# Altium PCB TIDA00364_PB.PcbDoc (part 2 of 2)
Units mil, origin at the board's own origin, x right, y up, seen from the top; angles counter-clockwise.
Board outline 10630 x 4425 mil, 2 copper layers (Top Layer, Metal), stack 128.78 mil thick; 244 components, 79 nets, 527 pads, 0 vias.
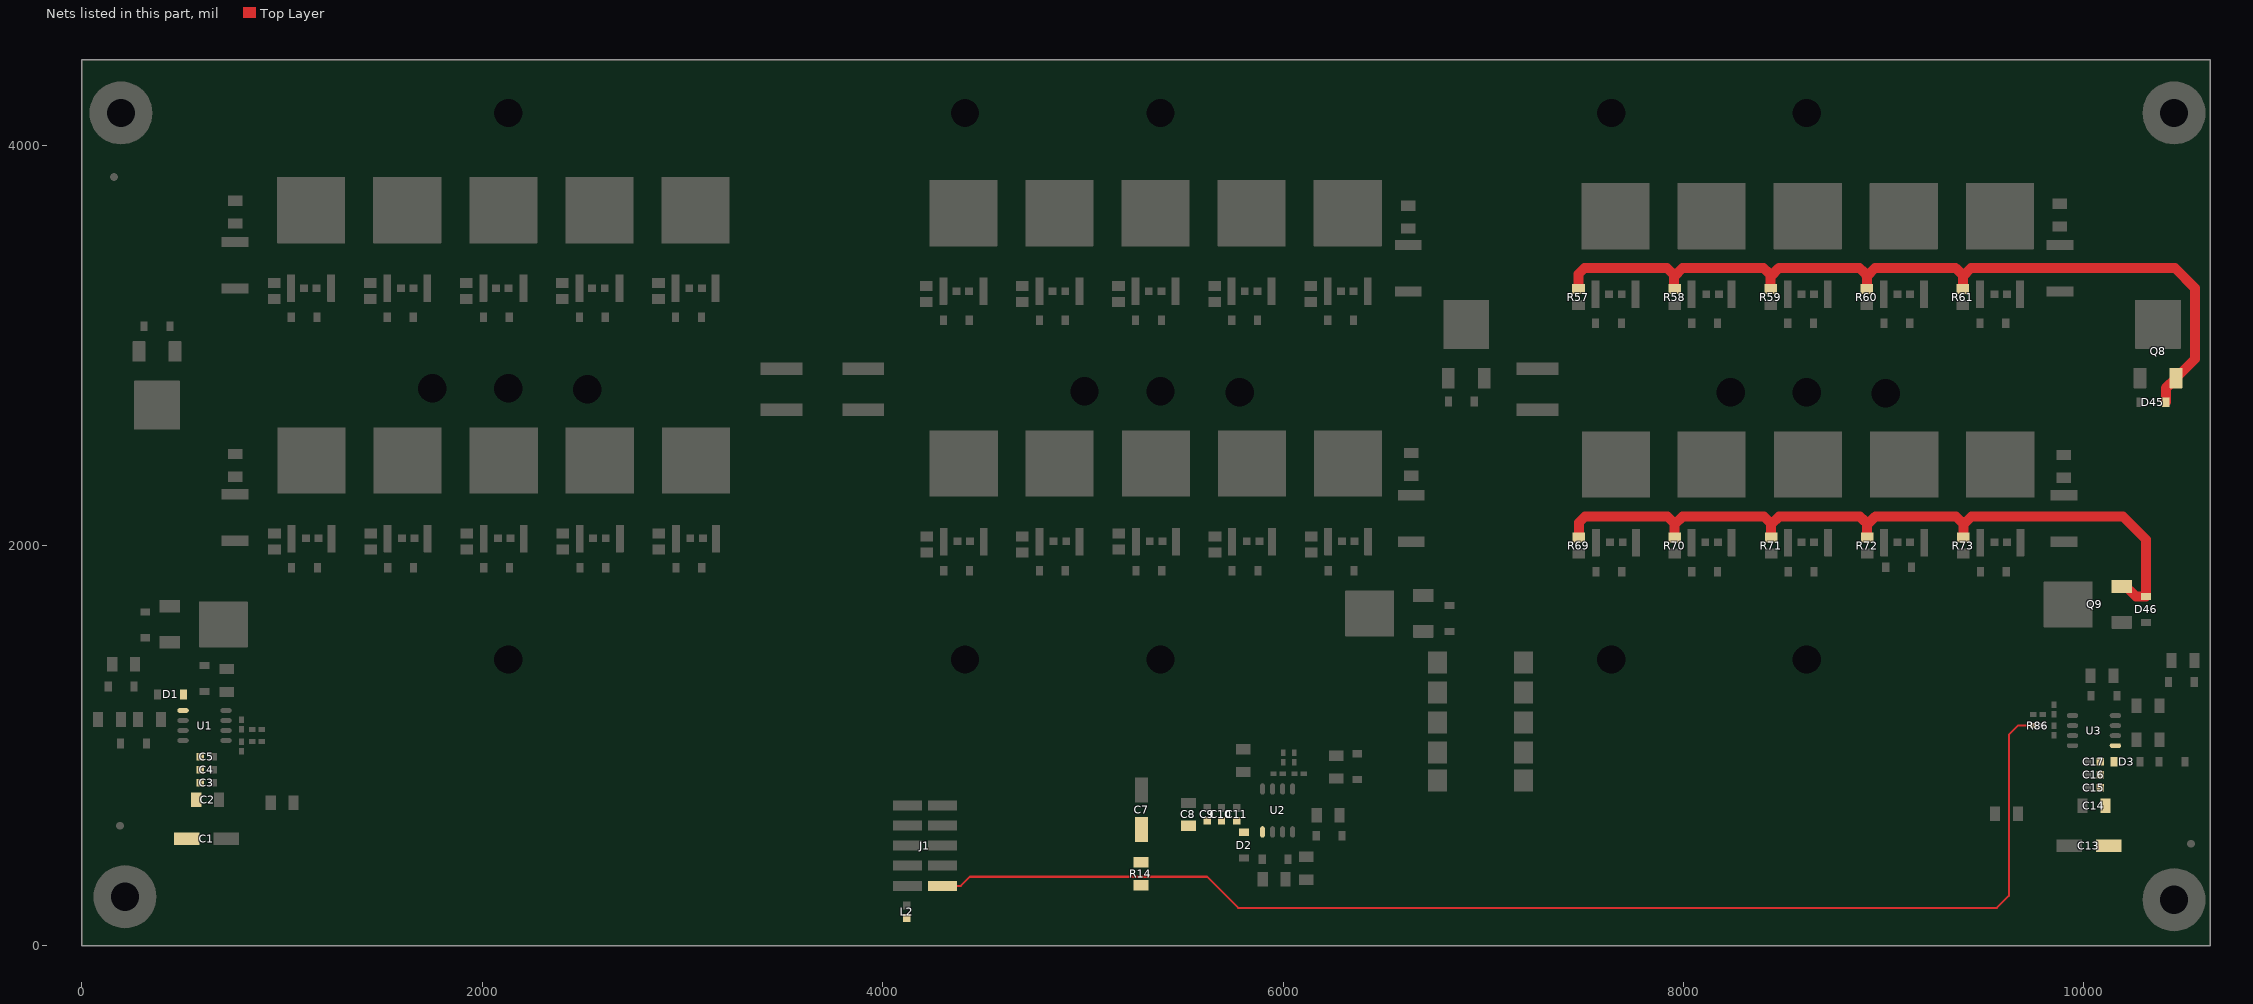
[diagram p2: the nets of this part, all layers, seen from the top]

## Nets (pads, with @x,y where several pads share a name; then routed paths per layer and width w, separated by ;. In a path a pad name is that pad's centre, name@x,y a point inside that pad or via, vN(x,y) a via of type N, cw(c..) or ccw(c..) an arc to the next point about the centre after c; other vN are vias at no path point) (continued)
PHW_PWM_HI_DRV: D45.1 Q8.3 R57.2 R58.2 R59.2 R60.2 R61.2 | length 4225.8
  Top Layer w30: D45.1@10408.94,2715.53 D45.1@10409.23,2715.83
  Top Layer w50: R57.2@7475.28,3280 7475.28,3355.32 7505.75,3385.79 7917.6,3385.79 7937.6,3365.79 7955.89,3347.5 ; R58.2@7953.39,3280 7953.39,3345 7955.89,3347.5 ; R59.2@8435.28,3295 8435.28,3345 8437.78,3347.5 ; R60.2@8915.28,3280 8915.28,3345 8917.78,3347.5 ; R61.2@9395.28,3280 9395.28,3345 9397.78,3347.5 ; D45.1@10408.94,2715.53 10408.94,2785.32 Q8.3@10459.76,2836.14 10555,2931.38 10555,3285 10454.21,3385.79 9436.06,3385.79 9397.78,3347.5 ; 7955.89,3347.5 7994.17,3385.79 8399.49,3385.79 8420.12,3365.16 8437.78,3347.5 ; 8437.78,3347.5 8476.06,3385.79 8879.49,3385.79 8895.75,3369.53 8917.78,3347.5 ; 8917.78,3347.5 8956.06,3385.79 9359.49,3385.79 9384.49,3360.79 9397.78,3347.5
PHW_PWM_LO: J1.10 R86.2 | length 6380.3
  Top Layer w10: J1.10@4297.4,300 4390,300 4435,345 5620,345 5775,190 9565,190 9625,250 9625,1055 9670,1100 R86.2@9746.38,1100
PHW_PWM_LO_DRV: D46.1 Q9.3 R69.2 R70.2 R71.2 R72.2 R73.2 | length 3781.9
  Top Layer w30: Q9.3@10188.86,1794.76 10210.24,1794.76 Q9.3@10232.5,1772.5
  Top Layer w50: R69.2@7477.17,2039.21 7477.17,2114.53 7507.64,2145 7919.49,2145 7939.49,2125 7957.78,2106.71 ; R70.2@7955.28,2039.21 7955.28,2104.21 7957.78,2106.71 ; R71.2@8437.17,2054.21 8437.17,2104.21 8439.67,2106.71 ; R72.2@8917.17,2039.21 8917.17,2104.21 8919.67,2106.71 ; R73.2@9397.17,2039.21 9397.17,2104.21 9399.67,2106.71 ; Q9.3@10232.5,1772.5 10260.53,1744.47 D46.1@10310,1744.47 10310,2030 10195,2145 9437.95,2145 9399.67,2106.71 ; 7957.78,2106.71 7996.06,2145 8401.38,2145 8422.01,2124.37 8439.67,2106.71 ; 8439.67,2106.71 8477.95,2145 8881.38,2145 8897.64,2128.74 8919.67,2106.71 ; 8919.67,2106.71 8957.95,2145 9361.38,2145 9386.38,2120 9399.67,2106.71
VDD: C1.1 C2.1 C3.2 C4.1 C5.1 C7.1 C8.1 C9.2 C10.1 C11.1 C13.1 C14.1 C15.2 C16.1 C17.1 D1.2 D2.2 D3.2 L2.2 R14.1 R14.2 U1.1 U2.1 U3.1
pads on no net: FID1.1 FID2.1 FID3.1 H1. H2. H3. H4. H5. H6. H7. H8. H22.0 H23.0 H26.0 H27.0 H28.0 H29.0 H30.0 H31.0 H32.0 H33.0 H34.0 H35.0 H36.0 H37.0 H38.0

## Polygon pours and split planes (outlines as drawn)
48V on Top Layer "48V_L01_P294" (solid, remove dead copper, pour order 294): 3305,3490 3350,3445 3370,3425 3370,2860 3370,2834.3 3379.3,2825 4000,2825 4020,2845 4020,3440 4045,3465 4050,3470 4340,3470 6470,3470 6495,3495 6495,3655 6510,3670 6750,3670 6765,3655 6765,3495 6780,3480 7100,3480 7130,3450 7140,3440 7140,2860 7140,2835 7150,2825 7365.7,2825 7385.7,2845 7385.7,3129.3 7385,3130 7385,3445 7400,3460 7580,3460 9745,3460 9755,3470 9755,3670 9765,3680 10200,3680 10230,3710 10230,4365 10205,4390 425,4390 405,4370 405,3700 415,3690 895,3690 915,3670 915,3530 955,3490
48V_RTN on Top Layer "48V_RTN_L01_P292" (solid, remove dead copper, pour order 292): 7135,2080 7135,2705 7155,2725 7365.7,2725 7385.7,2705 7390,2700.7 7390,2025 7135,2025
48V_RTN on Top Layer "48V_RTN_L01_P290" (solid, remove dead copper, pour order 290): 3965.98,2735 3405,2735 3375,2705 3370,2700 3370,2585 3370,2135 3330,2095 3310,2075 3310,2070 4050,2070 4055,2075 4020,2110 4020,2210 4020,2725 4010,2735
PHASE_W on Top Layer "PHASE_W_L01_P288" (solid, remove dead copper, pour order 288): 9640,2225 9740,2225 9755,2240 9755,2400 9775,2420 9940,2420 9960,2440 9960,3312.99 9942.99,3330 9600,3330 9590,3320 9590,3045 9575,3030 9335,3030 9315,3050 9310,3055 9310,3100 9310,3310 9290,3330 9120,3330 9110,3320 9110,3135 9110,3040 9100,3030 8855,3030 8835,3050 8830,3055 8830,3225 8830,3315 8810,3335 8640,3335 8630,3325 8630,3040 8620,3030 8365,3030 8350,3045 8350,3320 8340,3330 8160,3330 8150,3320 8150,3035 8145,3030 7885,3030 7870,3045 7870,3300 7845,3325 7680,3325 7670,3315 7670,3045 7655,3030 7500,3030 7460,2990 7460,2245 7480,2225
PHASE_V on Top Layer "PHASE_V_L01_P286" (solid, remove dead copper, pour order 286): 6190,2220 6480,2220 6500,2240 6500,2420 6510,2430 6675,2430 6685,2440 6685,2510 6665,2530 6640,2555 6640,2725 6640,3085 6700,3145 6700,3325 6680,3345 6340,3345 6335,3340 6330,3335 6330,3215 6330,3055 6320,3045 6070,3045 6060,3055 6060,3340 6050,3350 5860,3350 5850,3340 5850,3055 5840,3045 5590,3045 5575,3060 5575,3320 5550,3345 5380,3345 5370,3335 5370,3055 5360,3045 5105,3045 5095,3055 5095,3335 5080,3350 4900,3350 4890,3340 4890,3290 4890,3060 4875,3045 4630,3045 4615,3060 4615,3330 4600,3345 4420,3345 4410,3335 4410,3265 4410,3055 4400,3045 4100,3045 4080,3025 4080,2635 4080,2250 4110,2220 4125,2220 4820,2220
PHASE_U on Top Layer "PHASE_U_L01_P284" (solid, remove dead copper, pour order 284): 875,3320 695,3320 690,3315 690,2440 700,2430 915,2430 925,2420 925,2245 935,2235 3290,2235 3305,2250 3305,3325 3270,3360 3080,3360 3075,3355 3075,3070 3065,3060 2810,3060 2800,3070 2800,3355 2790,3365 2595,3365 2590,3360 2590,3065 2585,3060 2330,3060 2320,3070 2320,3350 2310,3360 2120,3360 2110,3350 2110,3070 2100,3060 1850,3060 1840,3070 1840,3350 1825,3365 1640,3365 1635,3360 1635,3075 1620,3060 1380,3060 1360,3080 1360,3340 1340,3360 1165,3360 1150,3345 1150,3075 1135,3060 890,3060 880,3070 880,3315 875,3320
48V_RTN on Top Layer "Top Layer-No Net 1" (solid, remove dead copper, pour order 254): 159 vertices, not listed, extent 30,165 10585,2110
NetC24_2 on Top Layer "Top Layer-No Net" (solid, remove dead copper, pour order 282): 6565,2390 6715,2390 6720,2385 6720,2215 6715,2210 6565,2210 6560,2215 6560,2385
NetC23_2 on Top Layer "Top Layer-No Net" (solid, remove dead copper, pour order 280): 6560,3640 6710,3640 6715,3635 6715,3460 6710,3455 6555,3455 6550,3460 6550,3635 6555,3640
VDD on Top Layer "VDD_L01_P252" (solid, remove dead copper, pour order 252): 613,460 454,460 454,71 475,50 10170,50 10190,70 10190,290 9705,290 9635,220 9575,160 9545,160 1080,160 965,275 940,300 705,300 645,300 615,330 613,332 613,460
VDD on Top Layer "Top Layer-No Net 1" (solid, pour order 240): 5155,635 5155,400 5165,390 5502,390 5649.64,537.64 5903.64,537.64 5911.64,545.64 5911.64,635.64 5900.64,646.64 5166.64,646.64
VDD on Top Layer "Top Layer-No Net 1" (solid, pour order 238): 4465,325 4275,135 4465,135 5605,135 5795,135 5605,325
48V_RTN on Top Layer "Top Layer-No Net 1" (solid, remove dead copper, pour order 236): 5954.6,752.93 5934.7,752.93 5930,757.64 5930,827.64 5915,842.64 5820,842.64 5815,837.64 5815,685 5800,670 5075,670 5050,645 5050,490 5030,470 5010,470 4385,470 4235,470 4220,485 4220,545 4225,550 4465,550 4475,560 4475,900 5965,900 5965,763.33
48V_RTN on Top Layer "Top Layer-No Net 1" (solid, pour order 234): 864,1151 642,1151 634.39,1143.39 634.39,340.61 645,330 940,330 970,360 970,955 940,985 690,985 675,1000 675,1089 697,1111 876,1111 880,1115 880,1145 875,1150 865,1150
NetJ1_9 on Top Layer "Top Layer-No Net 1" (solid, pour order 232): 4040,345 4195,345 4200,340 4200,190 4190,180 4035,180 4025,190 4025,335 4035,345
NetC18_1 on Top Layer "Top Layer-No Net 1" (solid, pour order 224): 10350,1240 10350,995 10355,990 10465,990 10475,980 10480,975 10480,895 10480,882.5 10485,877.5 10537.5,877.5 10545,885 10545,1220 10520,1245 10355,1245 10350,1240
NetD3_1 on Top Layer "Top Layer-No Net 1" (solid, pour order 222): 10135,1070 10290,1070 10295,1065 10295,978 10311,962 10398,962 10405,955 10405,882.5 10400,877.5 10237.5,877.5 10225,890 10225,1030 10215,1040 10130,1040 10125,1045 10125,1065 10130,1070
VDD on Top Layer "Top Layer-No Net 1" (solid, remove dead copper, pour order 214): 568,940 568,812.98 533.08,778.06 454,698.98 454,482 454,419 470,403 610,403 613,406 613,791 614,792 614,833 614,1179 606,1187 557,1187 546,1198 539,1205 539,1262 539,1292 533,1298 484,1298 474,1288 474,1170 483,1161 549,1161 567,1143 568,1142
NetD1_1 on Top Layer "Top Layer-No Net 1" (solid, pour order 212): 470,1140 530,1140 535,1135 535,1115 530,1110 445,1110 425,1090 370,1035 370,975 362.93,967.93 307.07,967.93 300,975 300,1047.93 305,1052.93 317.93,1052.93 330,1065 335,1070 335,1255 335,1285.86 346.57,1297.43 422.57,1297.43 430,1290 430,1150 440,1140
NetC6_1 on Top Layer "Top Layer-No Net 1" (solid, pour order 210): 170,1175 170,970.49 172.57,967.93 212.93,967.93 225,980 225,1075.73 232.06,1082.79 302.79,1082.79 310,1090 310,1175 305,1180 175,1180
NetD38_1 on Top Layer "Top Layer-No Net 1" (solid, pour order 200): 7537.17,2089.21 7632.17,2089.21 7642.17,2079.21 7647.17,2074.21 7647.17,2009.21 7647.17,1844.21 7627.17,1824.21 7447.17,1824.21 7432.17,1839.21 7432.17,1984.21 7437.17,1989.21 7522.17,1989.21 7532.17,1999.21 7532.17,2084.21 7537.17,2089.21
NetD39_1 on Top Layer "Top Layer-No Net 1" (solid, pour order 198): 8015.28,2089.21 8110.28,2089.21 8120.28,2079.21 8125.28,2074.21 8125.28,2009.21 8125.28,1844.21 8105.28,1824.21 7925.28,1824.21 7910.28,1839.21 7910.28,1984.21 7915.28,1989.21 8000.28,1989.21 8010.28,1999.21 8010.28,2084.21 8015.28,2089.21
NetD40_1 on Top Layer "Top Layer-No Net 1" (solid, pour order 196): 8497.17,2089.21 8592.17,2089.21 8602.17,2079.21 8607.17,2074.21 8607.17,2009.21 8607.17,1844.21 8587.17,1824.21 8407.17,1824.21 8392.17,1839.21 8392.17,1984.21 8397.17,1989.21 8482.17,1989.21 8492.17,1999.21 8492.17,2084.21 8497.17,2089.21
NetD41_1 on Top Layer "Top Layer-No Net 1" (solid, pour order 194): 8977.17,2089.21 9072.17,2089.21 9082.17,2079.21 9087.17,2074.21 9087.17,2009.21 9087.17,1844.21 9067.17,1824.21 8887.17,1824.21 8872.17,1839.21 8872.17,1984.21 8877.17,1989.21 8962.17,1989.21 8972.17,1999.21 8972.17,2084.21 8977.17,2089.21
NetD42_1 on Top Layer "Top Layer-No Net 1" (solid, pour order 192): 9457.17,2089.21 9552.17,2089.21 9562.17,2079.21 9567.17,2074.21 9567.17,2009.21 9567.17,1844.21 9547.17,1824.21 9367.17,1824.21 9352.17,1839.21 9352.17,1984.21 9357.17,1989.21 9442.17,1989.21 9452.17,1999.21 9452.17,2084.21 9457.17,2089.21
NetD37_1 on Top Layer "Top Layer-No Net 1" (solid, pour order 190): 9455.28,3330 9550.28,3330 9560.28,3320 9565.28,3315 9565.28,3250 9565.28,3085 9545.28,3065 9365.28,3065 9350.28,3080 9350.28,3225 9355.28,3230 9440.28,3230 9450.28,3240 9450.28,3325 9455.28,3330
NetD36_1 on Top Layer "Top Layer-No Net 1" (solid, pour order 188): 8975.28,3330 9070.28,3330 9080.28,3320 9085.28,3315 9085.28,3250 9085.28,3085 9065.28,3065 8885.28,3065 8870.28,3080 8870.28,3225 8875.28,3230 8960.28,3230 8970.28,3240 8970.28,3325 8975.28,3330
NetD35_1 on Top Layer "Top Layer-No Net 1" (solid, pour order 186): 8495.28,3330 8590.28,3330 8600.28,3320 8605.28,3315 8605.28,3250 8605.28,3085 8585.28,3065 8405.28,3065 8390.28,3080 8390.28,3225 8395.28,3230 8480.28,3230 8490.28,3240 8490.28,3325 8495.28,3330
NetD34_1 on Top Layer "Top Layer-No Net 1" (solid, pour order 184): 8015.28,3330 8110.28,3330 8120.28,3320 8125.28,3315 8125.28,3250 8125.28,3085 8105.28,3065 7925.28,3065 7910.28,3080 7910.28,3225 7915.28,3230 8000.28,3230 8010.28,3240 8010.28,3325 8015.28,3330
NetD33_1 on Top Layer "Top Layer-No Net 1" (solid, pour order 182): 7535.28,3330 7630.28,3330 7640.28,3320 7645.28,3315 7645.28,3250 7645.28,3085 7625.28,3065 7445.28,3065 7430.28,3080 7430.28,3225 7435.28,3230 7520.28,3230 7530.28,3240 7530.28,3325 7535.28,3330
NetD28_1 on Top Layer "Top Layer-No Net 1" (solid, pour order 180): 4279.53,2094.21 4374.53,2094.21 4384.53,2084.21 4389.53,2079.21 4389.53,2014.21 4389.53,1849.21 4369.53,1829.21 4189.53,1829.21 4174.53,1844.21 4174.53,1989.21 4179.53,1994.21 4264.53,1994.21 4274.53,2004.21 4274.53,2089.21 4279.53,2094.21
NetD29_1 on Top Layer "Top Layer-No Net 1" (solid, pour order 178): 4757.64,2094.21 4852.64,2094.21 4862.64,2084.21 4867.64,2079.21 4867.64,2014.21 4867.64,1849.21 4847.64,1829.21 4667.64,1829.21 4652.64,1844.21 4652.64,1989.21 4657.64,1994.21 4742.64,1994.21 4752.64,2004.21 4752.64,2089.21 4757.64,2094.21
NetD30_1 on Top Layer "Top Layer-No Net 1" (solid, pour order 176): 5239.53,2094.21 5334.53,2094.21 5344.53,2084.21 5349.53,2079.21 5349.53,2014.21 5349.53,1849.21 5329.53,1829.21 5149.53,1829.21 5134.53,1844.21 5134.53,1989.21 5139.53,1994.21 5224.53,1994.21 5234.53,2004.21 5234.53,2089.21 5239.53,2094.21
NetD31_1 on Top Layer "Top Layer-No Net 1" (solid, pour order 174): 5719.53,2094.21 5814.53,2094.21 5824.53,2084.21 5829.53,2079.21 5829.53,2014.21 5829.53,1849.21 5809.53,1829.21 5629.53,1829.21 5614.53,1844.21 5614.53,1989.21 5619.53,1994.21 5704.53,1994.21 5714.53,2004.21 5714.53,2089.21 5719.53,2094.21
NetD32_1 on Top Layer "Top Layer-No Net 1" (solid, pour order 172): 6199.53,2094.21 6294.53,2094.21 6304.53,2084.21 6309.53,2079.21 6309.53,2014.21 6309.53,1849.21 6289.53,1829.21 6109.53,1829.21 6094.53,1844.21 6094.53,1989.21 6099.53,1994.21 6184.53,1994.21 6194.53,2004.21 6194.53,2089.21 6199.53,2094.21
NetD27_1 on Top Layer "Top Layer-No Net 1" (solid, pour order 170): 6197.64,3345 6292.64,3345 6302.64,3335 6307.64,3330 6307.64,3265 6307.64,3100 6287.64,3080 6107.64,3080 6092.64,3095 6092.64,3240 6097.64,3245 6182.64,3245 6192.64,3255 6192.64,3340 6197.64,3345
NetD26_1 on Top Layer "Top Layer-No Net 1" (solid, pour order 168): 5717.64,3345 5812.64,3345 5822.64,3335 5827.64,3330 5827.64,3265 5827.64,3100 5807.64,3080 5627.64,3080 5612.64,3095 5612.64,3240 5617.64,3245 5702.64,3245 5712.64,3255 5712.64,3340 5717.64,3345
NetD25_1 on Top Layer "Top Layer-No Net 1" (solid, pour order 166): 5237.64,3345 5332.64,3345 5342.64,3335 5347.64,3330 5347.64,3265 5347.64,3100 5327.64,3080 5147.64,3080 5132.64,3095 5132.64,3240 5137.64,3245 5222.64,3245 5232.64,3255 5232.64,3340 5237.64,3345
NetD24_1 on Top Layer "Top Layer-No Net 1" (solid, pour order 164): 4757.64,3345 4852.64,3345 4862.64,3335 4867.64,3330 4867.64,3265 4867.64,3100 4847.64,3080 4667.64,3080 4652.64,3095 4652.64,3240 4657.64,3245 4742.64,3245 4752.64,3255 4752.64,3340 4757.64,3345
NetD23_1 on Top Layer "Top Layer-No Net 1" (solid, pour order 162): 4277.64,3345 4372.64,3345 4382.64,3335 4387.64,3330 4387.64,3265 4387.64,3100 4367.64,3080 4187.64,3080 4172.64,3095 4172.64,3240 4177.64,3245 4262.64,3245 4272.64,3255 4272.64,3340 4277.64,3345
NetD18_1 on Top Layer "Top Layer-No Net 1" (solid, pour order 160): 1021.89,2109.21 1116.89,2109.21 1126.89,2099.21 1131.89,2094.21 1131.89,2029.21 1131.89,1864.21 1111.89,1844.21 960.79,1844.21 916.89,1888.11 916.89,2004.21 921.89,2009.21 1006.89,2009.21 1016.89,2019.21 1016.89,2104.21
NetD19_1 on Top Layer "Top Layer-No Net 1" (solid, pour order 158): 1501.89,2109.21 1596.89,2109.21 1606.89,2099.21 1611.89,2094.21 1611.89,2029.21 1611.89,1864.21 1591.89,1844.21 1411.89,1844.21 1396.89,1859.21 1396.89,2004.21 1401.89,2009.21 1486.89,2009.21 1496.89,2019.21 1496.89,2104.21 1501.89,2109.21
NetD20_1 on Top Layer "Top Layer-No Net 1" (solid, pour order 154): 1981.89,2109.21 2076.89,2109.21 2086.89,2099.21 2091.89,2094.21 2091.89,2029.21 2091.89,1864.21 2071.89,1844.21 1891.89,1844.21 1876.89,1859.21 1876.89,2004.21 1881.89,2009.21 1966.89,2009.21 1976.89,2019.21 1976.89,2104.21 1981.89,2109.21
NetD21_1 on Top Layer "Top Layer-No Net 1" (solid, pour order 152): 2461.89,2109.21 2556.89,2109.21 2566.89,2099.21 2571.89,2094.21 2571.89,2029.21 2571.89,1864.21 2551.89,1844.21 2371.89,1844.21 2356.89,1859.21 2356.89,2004.21 2361.89,2009.21 2446.89,2009.21 2456.89,2019.21 2456.89,2104.21 2461.89,2109.21
NetD22_1 on Top Layer "Top Layer-No Net 1" (solid, pour order 150): 2941.89,2109.21 3036.89,2109.21 3046.89,2099.21 3051.89,2094.21 3051.89,2029.21 3051.89,1864.21 3031.89,1844.21 2851.89,1844.21 2836.89,1859.21 2836.89,2004.21 2841.89,2009.21 2926.89,2009.21 2936.89,2019.21 2936.89,2104.21 2941.89,2109.21
NetD17_1 on Top Layer "Top Layer-No Net 1" (solid, pour order 148): 2940,3360 3035,3360 3045,3350 3050,3345 3050,3280 3050,3115 3030,3095 2850,3095 2835,3110 2835,3255 2840,3260 2925,3260 2935,3270 2935,3355 2940,3360
NetD16_1 on Top Layer "Top Layer-No Net 1" (solid, remove dead copper, pour order 146): 2460,3360 2555,3360 2565,3350 2570,3345 2570,3280 2570,3115 2550,3095 2370,3095 2355,3110 2355,3255 2360,3260 2445,3260 2455,3270 2455,3355 2460,3360
NetD15_1 on Top Layer "Top Layer-No Net 1" (solid, pour order 144): 1980,3360 2075,3360 2085,3350 2090,3345 2090,3280 2090,3115 2070,3095 1890,3095 1875,3110 1875,3255 1880,3260 1965,3260 1975,3270 1975,3355 1980,3360
NetC12_1 on Top Layer "Top Layer-No Net" (solid, remove dead copper, pour order 124): 6039,473.64 5986.64,473.64 5984.64,471.64 5984.64,288.64 5986.64,286.64 6155.76,286.64 6162.28,293.15 6162.28,350.36 6156.64,356 6048.13,356 6043,361.13 6043,469.64
NetD2_1 on Top Layer "Top Layer-No Net" (solid, remove dead copper, pour order 121): 5939.64,599.39 5937.39,599.39 5932.64,594.64 5932.64,537.64 5910.64,515.64 5799.64,515.64 5775.64,515.64 5768.64,508.64 5768.64,298.64 5779.64,287.64 5931.64,287.64 5935.64,291.64 5935.64,478.64 5961.64,504.64 5961.64,595.64 5957.88,599.39
NetC36_2 on Top Layer "Top Layer-No Net" (solid, remove dead copper, pour order 128): 701,2382 827,2382 835,2374 835,2226 821,2212 707,2212 693,2226 693,2374
NetC29_2 on Top Layer "Top Layer-No Net" (solid, remove dead copper, pour order 127): 701,3650 824.99,3650 838,3636.99 838,3489 824,3475 707,3475 693,3489 693,3642
NetC25_2 on Top Layer "Top Layer-No Net" (solid, remove dead copper, pour order 129): 9830,3635 9940,3635 9950,3625 9950,3455 9945,3450 9826.81,3450 9810,3466.81 9810,3615
NetC26_2 on Top Layer "Top Layer-No Net" (solid, remove dead copper, pour order 136): 9825,2385 9975,2385 9980,2380 9980,2210 9975,2205 9825,2205 9820,2210 9820,2385 9825,2390
NetD13_1 on Top Layer "Top Layer-No Net 1" (solid, pour order 140): 1020,3360 1115,3360 1125,3350 1130,3345 1130,3280 1130,3115 1110,3095 930,3095 915,3110 915,3255 920,3260 1005,3260 1015,3270 1015,3355 1020,3360
NetD14_1 on Top Layer "Top Layer-No Net 1" (solid, remove dead copper, pour order 142): 1500,3360 1595,3360 1605,3350 1610,3345 1610,3280 1610,3115 1590,3095 1410,3095 1395,3110 1395,3255 1400,3260 1485,3260 1495,3270 1495,3355 1500,3360
VDD on Top Layer "Top Layer-No Net 1" (solid, pour order 220): 10175,1015 10125,1015 10060,950 10060,170 10120,170 10190,170 10190,585 10190,995 10190,1010 10185,1015
48V_RTN on Top Layer "Top Layer-No Net 1" (solid, pour order 228): 10040,940 10040,650 10000,610 10000,365 9975,340 9690,340 9670,360 9670,935 9680,945 9810,945 9830,965 9830,1065 9835,1070 9865,1070 9870,1065 9870,955 9880,945 10035,945

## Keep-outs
Keep-Out Layer:
  circle w10: c7638.36,1430 r91.91
  circle w10: c4411,1430 r91.91
  circle w10: c4411,4160 r91.91
  circle w10: c7638.36,4160 r91.91
  lines w10: 20,35 20,4405 10610,4405 10610,35 20,35
  text ".Layer_Name" at 534.92,-1255.86 h60

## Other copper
Top Layer:
  pour cut-out: 6215,230.39 6244.61,230.39 6245,230 6245,420 6305,480 7070,480 7120,480 7135,495 7135,480 7135,625 6260,625 6215,580
  pour cut-out: 6055.27,825 6129.45,825 6213.58,909.13 6309.13,909.13 6330,930 6330,775 6260,775 6190,705 6055,705
  pour cut-out: 636.96,1475.5 601.24,1475.5 575,1501.74 575,1445 630,1445 635,1450
  pour cut-out: 575,1460 115,1460 115,2050 120,2055 460,2055 460,1790 575,1675
  pour cut-out: 6905,1900 6890,1885 6930,1885 6930,2090 6905,2090 6890,2090 6880,2090 6890,2080 6905,2065
  pour cut-out: 10040,1045 10040,945 9880,945 9870,955 9870,1110 9870,1163.58 9879.84,1173.42 10002.02,1173.42 10005.27,1079.73
  pour cut-out: 10045,2080.79 10034.21,2080.79 10045,2070 10045,2035 10045,1740 10265,1740 10260,1745 10260,2070 10260,2080.79
  pour cut-out: 10265,1740 10265,1855 10139.76,1855 10045,1760.24 10045,1100 10265,1100
  pour cut-out: 824,1112.55 937.45,1112.55 1030,1020 1030,325 970,325 970,892.68 824,1038.68
  pour cut-out: 635,1475.5 823.99,1476.01 835,1465 835,1156.3 635,1156.3
  pour cut-out: 5867.89,722.69 5867.89,662.89 5865,660 5984.57,660 5985.63,661.06 5985.63,719.37 5985,720
  pour cut-out: 6820,1885 6820,575 6930,575 6930,1885
  pour cut-out: 7135,3255 7067.63,3255 7067.63,585 7135,585
  pour cut-out: 9823.69,1067.87 9652.13,1067.87 9650,1070 9650,1055 9814.35,1055 9823.69,1064.34
  pour cut-out: 6170.18,480 6170.18,210.18 6220,210 6215,215 6215,245 6215,480
  text ".layer_Name" at 549.92,-1245.37 h60
Metal:
  text ".Layer_Name" at 608.92,-1255.37 h60
Multi-Layer:
  pour cut-out: 30.2,464.8 40,455 400,455 415,440 415,45 30.39,45 29.99,45.4
  pour cut-out: 10260,430 10250,420 10250,35 10605,35 10605,430

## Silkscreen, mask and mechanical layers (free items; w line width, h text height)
Top Overlay:
  circle w10: c9010,2760 r161.25
  circle w10: c8615,2765 r161.25
  circle w10: c8235,2765 r161.25
  circle w10: c5782.64,2765 r161.25
  circle w10: c5387.64,2770 r161.25
  circle w10: c5007.64,2770 r161.25
  circle w10: c2525,2780 r161.25
  circle w10: c2130,2785 r161.25
  circle w10: c1750,2785 r161.25
  circle w10: c2130,4160 r231.19
  circle w10: c5387.64,4160 r231.19
  circle w10: c8615,4160 r231.19
  circle w10: c2130,1430 r231.19
  circle w10: c5387.64,1430 r231.19
  circle w10: c8615,1430 r231.19
  text "48V" at 5590,4305 h60
  text "48V" at 2345,4290 h60
  text "48V" at 8850,4280 h60
  text "PHASE_U" at 2750,2870 h60
  text "PHASE_V" at 6020,2860 h60
  text "PHASE_W" at 9240,2855 h60
  text "+48V_RTN" at 8420,1110 h60
  text "+48V_RTN" at 5170,1105 h60
  text "+48V_RTN" at 1930,1100 h60
  text "PHV_PWM_LO" at 4395,685 h30
  text "PHV_PWM_HI" at 3730,680 h30
  text "TIDA00364_PB_E1" at 2030,620 h40
  text "+48V_RTN" at 3785,585 h30
  text "+48V_RTN" at 4385,585 h30
  text "PHU_PWM_LO" at 3720,500 h30
  text "+48V_RTN" at 4405,495 h30
  text "PHU_PWM_HI" at 3730,400 h30
  text "PHW_PWM_HI" at 4410,400 h30
  text "+12V" at 3900,295 h30
  text "PHW_PWM_LO" at 4410,295 h30
  text ".layer_Name" at 575.92,-1243.37 h60
Bottom Overlay:
  text ".Layer_Name" at 534.92,-1255.86 h60
Top Paste:
  text ".Layer_Name" at 522.92,-1258.86 h60
Bottom Paste:
  text ".Layer_Name" at 522.92,-1258.86 h60
Top Solder:
  circle w60: c1750,2785 r120
  circle w60: c2130,2785 r120
  circle w60: c9010,2760 r120
  circle w60: c8615,2765 r120
  circle w60: c8235,2765 r120
  circle w60: c5782.64,2765 r120
  circle w60: c5387.64,2770 r120
  circle w60: c5007.64,2770 r120
  circle w60: c2525,2780 r120
  circle w120: c2130,4160 r150
  circle w120: c5387.64,4160 r150
  circle w120: c8615,4160 r150
  circle w120: c2130,1430 r150
  circle w120: c5387.64,1430 r150
  circle w120: c8615,1430 r150
  text ".Layer_Name" at 550.92,-1266.37 h60
Bottom Solder:
  text ".Layer_Name" at 597.92,-1262.37 h60
M1 Board Outline:
  the board outline again, w10
M2 Board Dimensions:
  rectangle: -205.58,-617.37 -80.58,-492.37
  rectangle: -80.58,-742.37 294.42,-617.37
  lines w7: -205.58,-587.37 794.42,-587.37 ; -80.58,-742.37 -80.58,-492.37 ; 44.42,-742.37 44.42,-492.37 ; 294.42,-742.37 294.42,-492.37 ; 544.42,-742.37 544.42,-492.37 ; -205.58,-742.37 794.42,-742.37 794.42,-492.37 -205.58,-492.37 -205.58,-742.37
  lines w10: -205.5,-791 -205.5,-771 ; -145.5,-801 -205.5,-781 ; -145.5,-761 -205.5,-781 ; 18.58,-781 -205.5,-781 ; 570.42,-781 794.5,-781 ; 734.5,-801 794.5,-781 ; 734.5,-761 794.5,-781 ; 794.5,-791 794.5,-771
  text "1000 (mil)" at 28.58,-816.99 h60
M3 3D STEP Top:
  text ".Layer_Name" at 534.92,-1255.86 h60
M4 3D STEP Bottom:
  text ".Layer_Name" at 534.92,-1255.86 h60
M5 Assembly Top:
  circle w10: c4147.4,700 r15.81
  lines w10: -334.08,-1327.53 6265.92,-1327.53 ; -334.08,-1124.2 6267.92,-1124.2 ; -334.08,-920.87 -334.08,-1530.87 3670.92,-1530.87 6267.92,-1530.87 6267.92,-920.87 -333.58,-920.87 -333.58,-1530.87 ; 2130.92,-1530.87 2130.92,-920.87 ; 3397.92,-1124.2 3397.92,-920.87 ; 4237.92,-1124.2 4237.92,-920.87 ; 4859.92,-1537.37 4859.92,-1334.53
  text "COMPONENTS MARKED 'DNP' SHOULD NOT BE POPULATED." at 1111.42,-715.87 h30
  text "ASSEMBLY VARIANT:" at 1110.92,-831.37 h30
  text ".VariantName" at 2146.92,-831.37 h30
  text "ALL ARTWORK VIEWED FROM TOP SIDE" at -270.58,-1053.03 h30
  text "BOARD #:" at 2205.92,-1053.03 h30
  text ".PRJ_Number" at 2751.42,-1053.03 h30
  text "REV:" at 3595.92,-1053.03 h30
  text ".PCB_Rev" at 3887.42,-1053.03 h30
  text "SVN REV:" at 4433.92,-1053.03 h30
  text ".VersionControl_RevNumber" at 4939.92,-1053.03 h30
  text ".layer_Name" at 492.92,-1235.37 h30
  text "TID #:" at 2190.92,-1238.03 h30
  text "LAYER NAME =" at -277.08,-1242.37 h30
  text ".PRJ_Number" at 2541.42,-1243.03 h30
  text ".plot_File_Name" at -279.08,-1431.37 h30
  text "GENERATED    :" at 2207.92,-1461.7 h30
  text ".Print_Date" at 3077.42,-1461.7 h30
  text ".Print_Time" at 3806.42,-1461.7 h30
  text "TEXAS INSTRUMENTS" at 5070.92,-1461.7 h30
M6 Assembly Bottom:
  lines w10: -334.58,-1124.7 6267.42,-1124.7 ; -332.58,-1328.03 6267.42,-1328.03 ; 1695.42,-1124.7 1695.42,-921.37 ; 2535.42,-1124.7 2535.42,-921.37 ; 3802.42,-1531.37 3802.42,-921.37 ; 4691.42,-1531.37 6266.92,-1531.37 6266.92,-921.37 -334.58,-921.37 -334.58,-1531.37 2262.42,-1531.37 6267.42,-1531.37 6267.42,-921.37
  text "COMPONENTS MARKED 'DNP' SHOULD NOT BE POPULATED." at 6059.92,-715.37 h30
  text ".VariantName" at 5015.92,-831.37 h30
  text "ASSEMBLY VARIANT:" at 6054.92,-831.37 h30
  text "SVN REV:" at 1499.42,-1053.53 h30
  text ".PCB_Rev" at 2045.92,-1053.53 h30
  text "REV:" at 2337.42,-1053.53 h30
  text ".PRJ_Number" at 3181.92,-1053.53 h30
  text "BOARD #:" at 3727.42,-1053.53 h30
  text "PCB VIEWED FROM BOTTOM SIDE" at 6203.92,-1053.53 h30
  text "TID #:" at 3759.08,-1228.03 h30
  text ".PRJ_Number" at 3408.58,-1233.03 h30
  text "LAYER NAME =" at 6198.92,-1238.37 h30
  text ".Layer_Name" at 5425.92,-1245.37 h30
  text "IGNORE ->" at 2505.77,-1255.86 h30
  text ".Print_Time" at 2126.92,-1462.2 h30
  text ".Print_Date" at 2855.92,-1462.2 h30
  text "GENERATED    :" at 3725.42,-1462.2 h30
  text ".plot_File_Name" at 5398.42,-1462.2 h30
  text "PLOT NAME =" at 6203.92,-1462.2 h30
M9 Title Sheet:
  drawing of 56 lines, arcs and shapes, not listed
  text "1" at 697.76,7639.13 h70
  text "2" at 3193.42,7639.13 h70
  text "3" at 5682.76,7639.13 h70
  text "4" at 8189.43,7639.13 h70
  text "5" at 10688.42,7639.13 h70
  text "6" at 13193.42,7639.13 h70
  text "A" at 19361.42,6671.13 h70
  text "A" at -458.58,6496.13 h70
  text "B" at 19361.42,4291.13 h70
  text "B" at -458.58,4116.13 h70
  text "C" at 19361.42,1916.13 h70
  text "C" at -458.58,1741.13 h70
  text "PROJECT TITLE:" at 16321.42,55.13 h45
  text ".PRJ_Title" at 16741.92,-81.37 h70
  text "DESIGNED FOR:" at 16321.42,-245.87 h45
  text ".PRJ_Customer" at 16371.42,-385.87 h70
  text "D" at 19361.42,-453.87 h70
  text "FILE NAME:" at 16321.42,-545.87 h45
  text "D" at -458.58,-628.87 h70
  text ".PCB_File_Name_No_Path" at 16371.42,-665.87 h70
  text "ENGINEER:" at 16321.42,-835.87 h45
  text "LAYOUT BY:" at 17826.42,-835.87 h45
  text ".PRJ_Engineer" at 16371.42,-990.86 h70
  text ".PCB_Layout" at 17876.92,-990.86 h70
  text "Texas Instruments (TI) and/or its licensors do not warrant the accuracy or completeness of this specification" at 6331.92,-1002.71 h45
  text "or any information contained therein. TI and/or its licensors do not warrant that this design will meet" at 6286.93,-1115.37 h45
  text "ALTIUM DESIGNER VERSION:" at 17826.42,-1145.87 h45
  text "the specifications, will be suitable for your application or fit for any particular purpose, or will operate in" at 6286.93,-1228.04 h45
  text ".print_Scale" at 16371.42,-1279.19 h70
  text ".Application_BuildNumber" at 17876.92,-1279.19 h70
  text "an implementation. TI and/or its licensors do not warrant that the design is production worthy. You should" at 6286.93,-1340.7 h45
  text "completely validate and test your design implementation to confirm the system functionality for your application." at 6331.92,-1453.37 h45
  text "6" at 18213.42,-1485.87 h70
  text "2" at 3193.42,-1660.87 h70
  text "3" at 5682.76,-1660.87 h70
  text "4" at 8189.43,-1660.87 h70
  text "5" at 10688.42,-1660.87 h70
M10 Fab Notes:
  drawing of 228 lines, arcs and shapes, not listed
  text "DESIGN INFORMATION" at 17358.94,6587.63 h60
  text "(REFER ALSO ARRAY/PANEL PROFILING INFORMATION)" at 16997.38,6425.92 h60
  text "BOARD SIZE" at 16311.38,6421.63 h60
  text "270MM" at 16773.7,6293.81 h60
  text "X" at 17279.38,6293.81 h60
  text "112.39MM" at 17510.7,6293.81 h60
  text "Number of Layers :" at 16714.38,6096.63 h60
  text "1" at 17809.19,6086.63 h60
  text "MIN. TRACK WIDTH:" at 16714.38,5957.63 h60
  text "10" at 17810.62,5957.64 h60
  text "MIL" at 17965.38,5957.63 h60
  text "8" at 17805,5835 h60
  text "MIN. CLEARANCE:" at 16714.38,5825.63 h60
  text "MIL" at 17965.38,5825.63 h60
  text "MIN. VIA DRILL SIZE:" at 16714.38,5693.63 h60
  text "5.90 MIL" at 17409.38,5551.92 h60
  text "MINIMUM ANNULAR RING" at 16385.15,5547.64 h60
  text "EXTERNAL" at 18117.38,5547.64 h60
  text "PER" at 16585.15,5429.64 h60
  text "IPC-D-275 CLASS 2 LEVEL C" at 16805.15,5429.63 h60
  text "MIL, HOLES" at 18293.38,5317.35 h60
  text "+/-" at 17900.92,5316.63 h60
  text "+/-" at 18754.92,5316.63 h60
  text "REGISTRATION TOLERANCES:" at 16385.15,5311.63 h60
  text "METAL" at 17584.92,5311.63 h60
  text "5" at 18161.12,5311.64 h60
  text "3" at 18994.12,5311.64 h60
  text "MIL" at 19110.38,5311.63 h60
  text "MATERIAL:" at 16310.38,5102.18 h60
  text "FR-4 High Tg" at 17296.82,4961.84 h60
  text "Thermal Clad" at 18570,4955 h60
  text "FR-408" at 16731.38,4953.27 h60
  text "OTHER" at 18219.38,4953.27 h60
  text "X" at 18004.45,4948.27 h60
  text "118MIL (3.0mm) +/-10%" at 17051.48,4790.56 h60
  text "THICKNESS:" at 16385.15,4786.27 h60
  text "X" at 16923.32,4786.27 h60
  text "OTHER" at 18336.38,4786.27 h60
  text "TOLERANCE:" at 16385.15,4628.27 h60
  text "X" at 17224.45,4628.27 h60
  text "ANSI IPC-6012 TYPE 3 CLASS 2" at 17411.4,4628.27 h60
  text "OTHER +/-" at 17411.38,4472.27 h60
  text "BOW & TWIST:" at 16385.15,4315.27 h60
  text "X" at 17224.45,4315.27 h60
  text "ANSI IPC-6012 TYPE 3 CLASS 2" at 17411.4,4315.27 h60
  text "OTHER +/-" at 17411.38,4156.76 h60
  text "COPPER THICKNESS (FINISHED):" at 16310.38,4021.27 h60
  text "X" at 18525,3870 h60
  text "1.4MIL (1oz)" at 17190.38,3868.56 h60
  text "2MIL (1.4oz)" at 17957.38,3868.56 h60
  text "2.8MIL (2oz)" at 18684.38,3868.56 h60
  text "OUTER:" at 16667.38,3864.27 h60
  text "1.4MIL (1oz)" at 17190.38,3711.56 h60
  text "2.8MIL (2oz)" at 17957.38,3711.56 h60
  text "N/A" at 18683.92,3711.92 h60
  text "INNER SIGNAL:" at 16378.3,3707.27 h60
  text "DRILLING:" at 16310.38,3568.27 h60
  text "REFERENCE:" at 16385.15,3451.27 h60
  text "X" at 17033.38,3451.27 h60
  text "AS SHOWN" at 17220.38,3451.27 h60
  text "X" at 17934.38,3451.27 h60
  text "NC_DRILL FILES" at 18071.38,3451.27 h60
  text "PTH MIN COPPER THICKNESS:" at 16385.15,3293.27 h60
  text "1MIL" at 17872.38,3293.27 h60
  text "OTHER" at 18369.38,3293.27 h60
  text "BOARD FINISH:" at 16310.38,3134.27 h60
  text "SILKSCREEN:" at 16465.6,3016.27 h60
  text "X" at 17414.38,3016.27 h60
  text "TOP" at 17540.38,3016.27 h60
  text "BOTTOM" at 18051.38,3016.27 h60
  text "SILKSCREEN COLOR:" at 16465.6,2849.27 h60
  text "X" at 17413.34,2849.27 h60
  text "WHITE" at 17540.38,2849.27 h60
  text "OTHER" at 18051.38,2849.27 h60
  text "SOLDER RESIST COLOR:" at 16465.6,2679.27 h60
  text "X" at 17033.34,2520.07 h60
  text "GREEN" at 17160.38,2520.07 h60
  text "BLUE" at 17751.38,2520.07 h60
  text "OTHER" at 18289.38,2520.07 h60
  text "IMMERSION GOLD (ENIG)" at 17371.38,2331.56 h60
  text "ENEPIG" at 18708.92,2328.27 h60
  text "SURFACE FINISH:" at 16310.38,2327.27 h60
  text "X" at 17184.43,2327.27 h60
  text "IMM. TIN/SILVER OR EQUIV" at 16639.92,2170.27 h60
  text "OTHER" at 18071.38,2170.27 h60
  text "ARRAY/PANEL:" at 16310.38,1991.27 h60
  text "CUT AND TRIM PER MECH LAYER 1" at 17371.38,1986.99 h60
  text "N.C. ROUTE" at 17371.38,1835.27 h60
  text "X" at 18050.38,1835.27 h60
  text "V. SCORE" at 18237.38,1835.27 h60
  text "CERTIFICATION:" at 16310.38,1698.27 h60
  text "MATERIALS AND WORKMANSHIP FOR ALL PCBS" at 17035.38,1698.27 h60
  text "TO MEET OR EXCEED THE REQUIREMENTS OF:" at 17035.38,1600.27 h60
  text "X" at 16661.88,1463.77 h60
  text "ANSI IPC-A-600F CLASS ->" at 16800.88,1463.77 h60
  text "X" at 18439.94,1463.77 h60
  text "2" at 18558.88,1463.77 h60
  text "1" at 18243.88,1462.27 h60
  text "3" at 18912.88,1462.27 h60
  text "X" at 16663.94,1304.27 h60
  text "UL 94V-0" at 16800.88,1304.27 h60
  text "X" at 17475.94,1304.27 h60
  text "RoHS" at 17612.88,1304.27 h60
  text "OTHER" at 18257.28,1304.27 h60
  text "PER ORDER" at 18654.34,1304.27 h60
  text "VIA TENTING:" at 17527.92,1170.63 h60
  text "YES" at 18065,1170 h60
  text "NO" at 18400,1165 h60
  text "ADDITIONAL REQUIREMENTS:" at 16310.38,1163.27 h60
  text "MICROSECTION:" at 16385.15,1048.27 h60
  text "YES" at 17290.88,1048.27 h60
  text "IMPEDANCE CONTROL:" at 17549.92,1041.63 h60
  text "YES" at 18525,1040 h60
  text "X" at 19050,1035 h60
  text "NO" at 18880,1025 h60
  text "REQUIRED" at 18152.38,892.13 h60
  text "BARE BOARD ELEC. TEST:" at 16385.15,889.27 h60
  text "NONE" at 17690.88,889.27 h60
  text "X" at 18025.38,889.27 h60
  text "PER ORDER" at 18744.38,889.27 h60
  text "MANUFACTURER'S UL:" at 16385.15,732.27 h60
  text "RAIL" at 17550.88,727.99 h60
  text "METAL" at 18042.69,727.99 h60
  text "X" at 18417.92,727.63 h60
  text "SILK" at 18554.38,727.99 h60
M11 Gerber Information:
  lines w10: -334.08,-1327.53 6265.92,-1327.53 ; -334.08,-1124.2 6267.92,-1124.2 ; -334.08,-920.87 -334.08,-1530.87 3670.92,-1530.87 6267.92,-1530.87 6267.92,-920.87 -333.58,-920.87 -333.58,-1530.87 ; 2130.92,-1530.87 2130.92,-920.87 ; 3397.92,-1124.2 3397.92,-920.87 ; 4237.92,-1124.2 4237.92,-920.87 ; 4859.92,-1537.37 4859.92,-1334.53
  text "BOARD #:" at 2205.92,-1053.03 h60
  text ".PRJ_Number" at 2751.42,-1053.03 h40
  text "REV:" at 3595.92,-1053.03 h60
  text ".PCB_Rev" at 3887.42,-1053.03 h60
  text "SVN REV:" at 4433.92,-1053.03 h60
  text ".VersionControl_RevNumber" at 4939.92,-1053.03 h60
  text "ALL ARTWORK VIEWED FROM TOP SIDE" at -271.58,-1059.03 h60
  text "LAYER NAME =" at -273.08,-1242.37 h60
  text ".PRJ_Number" at 2541.42,-1243.03 h40
  text "TID #:" at 2190.92,-1248.03 h60
  text ".plot_File_Name" at -281.08,-1441.37 h60
  text "GENERATED    :" at 2207.92,-1461.7 h60
  text ".Print_Date" at 3077.42,-1461.7 h60
  text ".Print_Time" at 3806.42,-1461.7 h60
  text "TEXAS INSTRUMENTS" at 5070.92,-1461.7 h60
M12 Stackup:
  lines w10: 11455,730 12290,730 ; 11455,825 12290,825 ; 11455,855 12290,855 ; 12295,610 12915,610 ; 11455,670 12290,670 12290,700 11455,700 11455,670 ; 11455,765 12290,765 12290,790 11455,790 11455,765
  text "Layer Stack up" at 11655,895 h20
  text "Top Overlay" at 12305,855 h20
  text "Top Solder (0.01 mm)" at 12305,820 h20
  text "Top Layer (0.07 mm)" at 12305,770 h20
  text "Dilelectric material (0.1 mm)" at 12305,725 h20
  text "Metal Substrate (2.8 mm)" at 12305,675 h20
  text "3 mm" at 12435,555 h20
  text "Board Thicknees is 3 mm" at 11485,405 h20
  text "Copper Thicknees is 2oz" at 11485,360 h20
M13 Component Bodies Top:
  text ".Layer_Name" at 534.92,-1255.86 h60
M14 Component Bodies Bottom:
  text ".Layer_Name" at 534.92,-1255.86 h60
M15 Courtyards Top:
  text ".Layer_Name" at 534.92,-1255.86 h60
M16 Courtyards Bottom:
  text ".Layer_Name" at 534.92,-1255.86 h60
Drill Drawing:
  text "Drill Table" at 11465,3870 h60
  text "FOR NPTH DRILL +/-2MIL" at 11470,3750 h60
  text ".legend" at 11462.92,3632.63 h60
  text ".layer_Name" at 639.92,-1239.37 h60

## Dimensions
10630,4425 to 10630,0 on M2 Board Dimensions
0,4425 to 10630,4425 on M2 Board Dimensions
